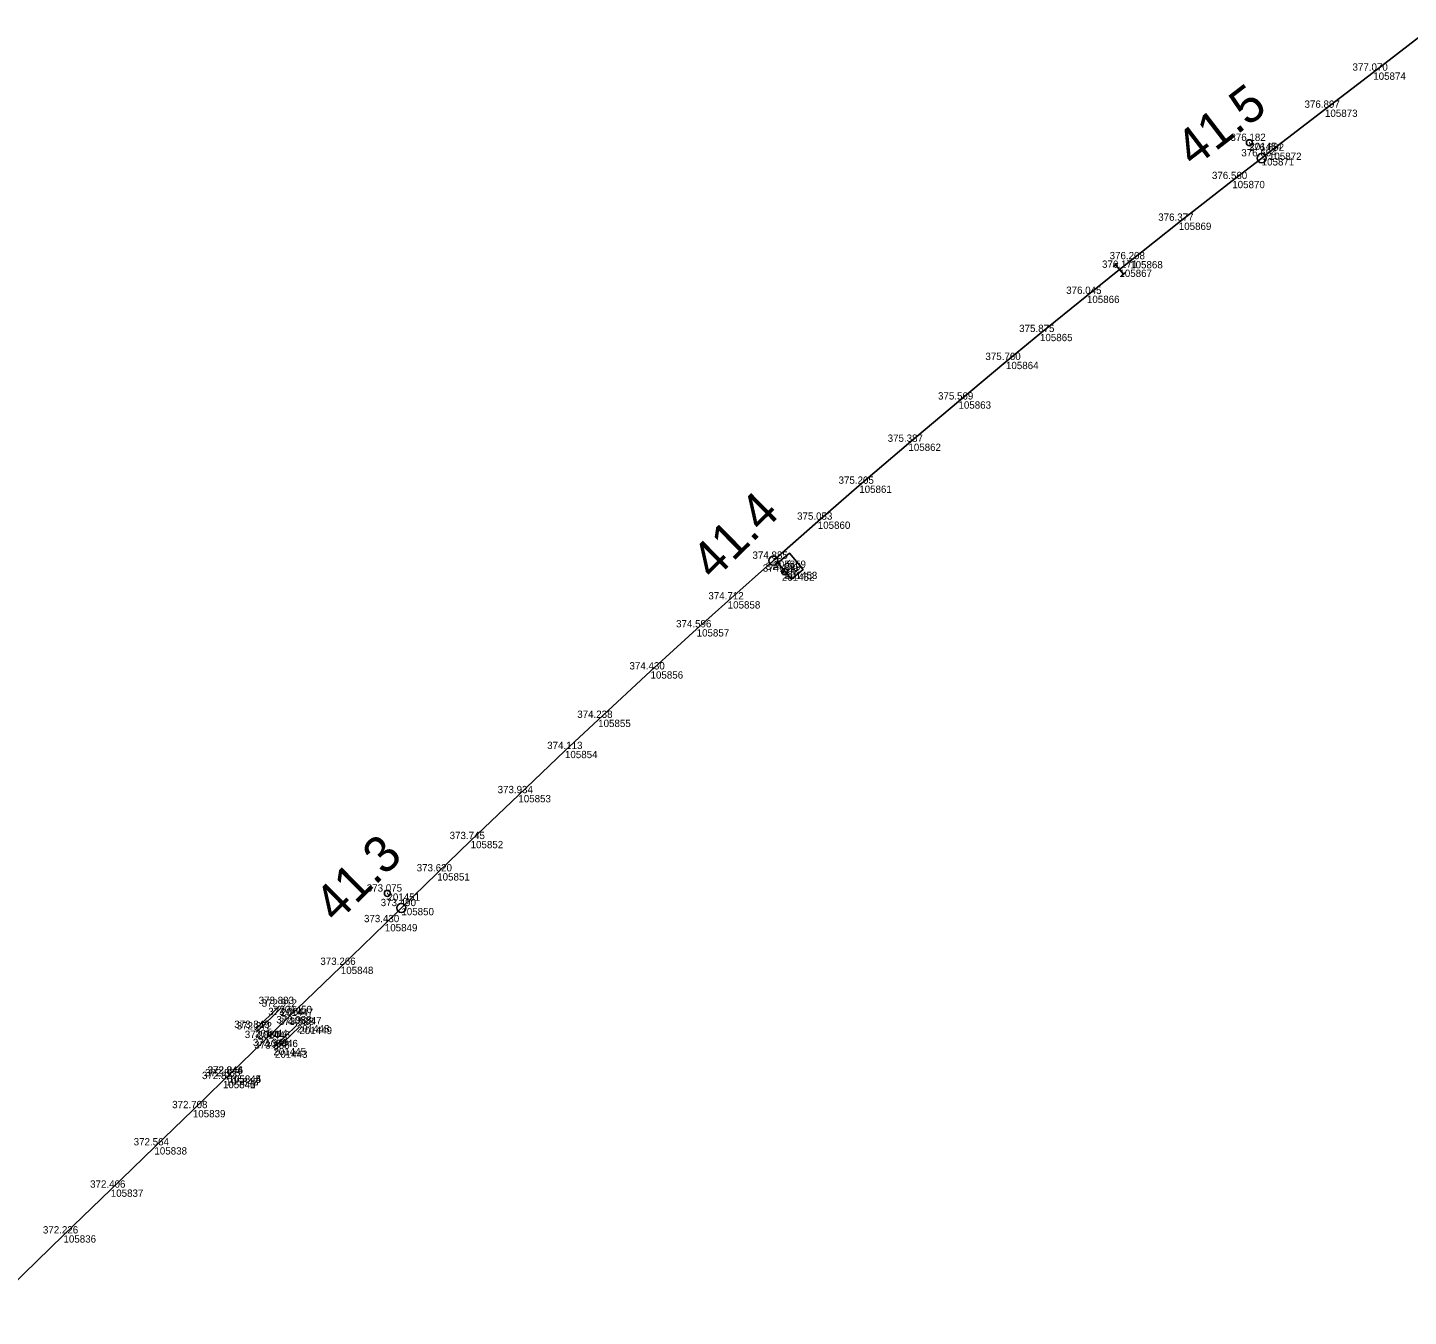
# Model space of a CAD drawing. Extents: x -514522 to -512811, y -1144589 to -1143575.
# Drawn here: x -514321 to -514094, y -1144405.9 to -1144194 of the extents above; entities that cross this region are included whole.
import ezdxf

# ---------------------------------------------------------------- set-up
doc = ezdxf.new("R2010")
doc.units = 0
for name, color, linetype in [('Vrstva 1', 7, 'Continuous'), ('Vrstva 17', 7, 'Continuous'), ('Vrstva 19', 7, 'Continuous'), ('Vrstva 3', 7, 'Continuous'), ('Vrstva 4', 7, 'Continuous'), ('Vrstva 60', 7, 'Continuous'), ('Vrstva 61', 7, 'Continuous'), ('Vrstva 7', 7, 'Continuous')]:
    doc.layers.add(name, color=color, linetype=linetype)

msp = doc.modelspace()

# ---------------------------------------------------------------- linework, layer by layer
at = {"layer": 'Vrstva 1'}
for p, q in [((-514099.77, -1144201.42), (-514090.17, -1144194.04)), ((-514107.71, -1144207.52), (-514099.77, -1144201.42)), ((-514116.92, -1144214.6), (-514107.71, -1144207.52)), ((-514118.11, -1144215.51), (-514116.92, -1144214.6)), ((-514122.95, -1144219.24), (-514118.11, -1144215.51)), ((-514131.74, -1144226.1), (-514122.95, -1144219.24)), ((-514139.73, -1144232.42), (-514131.74, -1144226.1)), ((-514141.5, -1144233.83), (-514139.73, -1144232.42)), ((-514146.84, -1144238.12), (-514141.5, -1144233.83)), ((-514154.56, -1144244.39), (-514146.84, -1144238.12)), ((-514160.15, -1144248.99), (-514154.56, -1144244.39)), ((-514167.96, -1144255.49), (-514160.15, -1144248.99)), ((-514176.19, -1144262.44), (-514167.96, -1144255.49)), ((-514184.27, -1144269.34), (-514176.19, -1144262.44)), ((-514191.09, -1144275.25), (-514184.27, -1144269.34)), ((-514198.39, -1144281.67), (-514191.09, -1144275.25)), ((-514205.89, -1144288.35), (-514198.39, -1144281.67)), ((-514211, -1144292.95), (-514205.89, -1144288.35)), ((-514218.58, -1144299.87), (-514211, -1144292.95)), ((-514227.19, -1144307.83), (-514218.58, -1144299.87)), ((-514232.65, -1144312.95), (-514227.19, -1144307.83)), ((-514240.31, -1144320.21), (-514232.65, -1144312.95)), ((-514248.16, -1144327.76), (-514240.31, -1144320.21)), ((-514253.65, -1144333.07), (-514248.16, -1144327.76)), ((-514259.54, -1144338.78), (-514253.65, -1144333.07)), ((-514262.26, -1144341.42), (-514259.54, -1144338.78)), ((-514269.5, -1144348.44), (-514262.26, -1144341.42)), ((-514278.02, -1144356.7), (-514269.5, -1144348.44)), ((-514281.91, -1144360.46), (-514278.02, -1144356.7)), ((-514287.96, -1144366.32), (-514281.91, -1144360.46)), ((-514288.88, -1144367.22), (-514288.4, -1144366.75)), ((-514288.4, -1144366.75), (-514287.96, -1144366.32)), ((-514293.82, -1144372), (-514288.88, -1144367.22)), ((-514300.14, -1144378.12), (-514293.82, -1144372)), ((-514307.31, -1144385.07), (-514300.14, -1144378.12)), ((-514315.09, -1144392.6), (-514307.31, -1144385.07)), ((-514328.85, -1144405.93), (-514315.09, -1144392.6))]:
    msp.add_line(p, q, dxfattribs=at)
at = {"layer": 'Vrstva 17'}
for p, q in [((-514283.6, -1144358.8), (-514279.59, -1144354.87)), ((-514280.33, -1144362.22), (-514276.3, -1144358.32))]:
    msp.add_line(p, q, dxfattribs=at)
at = {"layer": 'Vrstva 19'}
for p, q in [((-514283.21, -1144359.05), (-514279.39, -1144355.32)), ((-514280.57, -1144361.79), (-514276.72, -1144358.04))]:
    msp.add_line(p, q, dxfattribs=at)
at = {"layer": 'Vrstva 3'}
for p, q in [((-514142.52, -1144233.38), (-514141.76, -1144232.74)), ((-514142.14, -1144233.06), (-514140.85, -1144234.59)), ((-514141.24, -1144234.91), (-514140.47, -1144234.27))]:
    msp.add_line(p, q, dxfattribs=at)
at = {"layer": 'Vrstva 4'}
msp.add_line((-514160.15, -1144248.99), (-514154.56, -1144244.39), dxfattribs=at)
at = {"layer": 'Vrstva 60'}
for p, q in [((-514099.77, -1144201.42), (-514099.77, -1144201.42)), ((-514107.71, -1144207.52), (-514107.71, -1144207.52)), ((-514120.13, -1144212.97), (-514120.13, -1144212.97)), ((-514116.92, -1144214.6), (-514116.92, -1144214.6)), ((-514118.11, -1144215.51), (-514118.11, -1144215.51)), ((-514122.95, -1144219.24), (-514122.95, -1144219.24)), ((-514131.74, -1144226.1), (-514131.74, -1144226.1)), ((-514139.73, -1144232.42), (-514139.73, -1144232.42)), ((-514141.5, -1144233.83), (-514141.5, -1144233.83)), ((-514146.84, -1144238.12), (-514146.84, -1144238.12)), ((-514154.56, -1144244.39), (-514154.56, -1144244.39)), ((-514160.15, -1144248.99), (-514160.15, -1144248.99)), ((-514167.96, -1144255.49), (-514167.96, -1144255.49)), ((-514176.19, -1144262.44), (-514176.19, -1144262.44)), ((-514184.27, -1144269.34), (-514184.27, -1144269.34)), ((-514191.09, -1144275.25), (-514191.09, -1144275.25)), ((-514198.39, -1144281.67), (-514198.39, -1144281.67)), ((-514196.99, -1144283.79), (-514196.99, -1144283.79)), ((-514196.52, -1144283.5), (-514196.52, -1144283.5)), ((-514205.89, -1144288.35), (-514205.89, -1144288.35)), ((-514211, -1144292.95), (-514211, -1144292.95)), ((-514218.58, -1144299.87), (-514218.58, -1144299.87)), ((-514227.19, -1144307.83), (-514227.19, -1144307.83)), ((-514232.65, -1144312.95), (-514232.65, -1144312.95)), ((-514240.31, -1144320.21), (-514240.31, -1144320.21)), ((-514248.16, -1144327.76), (-514248.16, -1144327.76)), ((-514253.65, -1144333.07), (-514253.65, -1144333.07)), ((-514261.83, -1144336.39), (-514261.83, -1144336.39)), ((-514259.54, -1144338.78), (-514259.54, -1144338.78)), ((-514262.26, -1144341.42), (-514262.26, -1144341.42)), ((-514269.5, -1144348.44), (-514269.5, -1144348.44)), ((-514279.59, -1144354.87), (-514279.59, -1144354.87)), ((-514279.39, -1144355.32), (-514279.39, -1144355.32)), ((-514278.02, -1144356.7), (-514278.02, -1144356.7)), ((-514283.6, -1144358.8), (-514283.6, -1144358.8)), ((-514283.21, -1144359.05), (-514283.21, -1144359.05)), ((-514276.72, -1144358.04), (-514276.72, -1144358.04)), ((-514276.3, -1144358.32), (-514276.3, -1144358.32)), ((-514281.91, -1144360.46), (-514281.91, -1144360.46)), ((-514280.57, -1144361.79), (-514280.57, -1144361.79)), ((-514280.33, -1144362.22), (-514280.33, -1144362.22)), ((-514288.4, -1144366.75), (-514288.4, -1144366.75)), ((-514288.4, -1144366.75), (-514288.4, -1144366.75)), ((-514287.96, -1144366.32), (-514287.96, -1144366.32)), ((-514287.95, -1144366.32), (-514287.95, -1144366.32)), ((-514288.88, -1144367.21), (-514288.88, -1144367.21)), ((-514288.88, -1144367.22), (-514288.88, -1144367.22)), ((-514293.82, -1144372), (-514293.82, -1144372)), ((-514300.14, -1144378.12), (-514300.14, -1144378.12)), ((-514307.31, -1144385.07), (-514307.31, -1144385.07)), ((-514315.09, -1144392.6), (-514315.09, -1144392.6))]:
    msp.add_line(p, q, dxfattribs=at)
at = {"layer": 'Vrstva 7'}
for p, q in [((-514120.18, -1144212.97), (-514120.08, -1144212.97)), ((-514196.99, -1144283.79), (-514196.51, -1144283.39)), ((-514196.57, -1144283.5), (-514196.47, -1144283.5)), ((-514261.88, -1144336.39), (-514261.78, -1144336.39))]:
    msp.add_line(p, q, dxfattribs=at)
msp.add_lwpolyline([(-514197.63, -1144282.05), (-514195.73, -1144280.46), (-514193.49, -1144283.13), (-514195.39, -1144284.73)], close=True, dxfattribs=at)
for centre, radius in [((-514120.13, -1144212.97), 0.5), ((-514118.11, -1144215.51), 0.75), ((-514198.39, -1144281.67), 0.75), ((-514196.52, -1144283.5), 0.5), ((-514261.83, -1144336.39), 0.5), ((-514259.54, -1144338.78), 0.75)]:
    msp.add_circle(centre, radius, dxfattribs=at)

# ---------------------------------------------------------------- texts
at = {"layer": 'Vrstva 60'}
for s, p in [('105874', (-514099.77, -1144202.62)), ('105873', (-514107.71, -1144208.72)), ('201454', (-514120.13, -1144214.17)), ('105872', (-514116.92, -1144215.8)), ('105871', (-514118.11, -1144216.71)), ('105870', (-514122.95, -1144220.44)), ('105869', (-514131.74, -1144227.3)), ('105868', (-514139.73, -1144233.62)), ('105867', (-514141.5, -1144235.03)), ('105866', (-514146.84, -1144239.32)), ('105865', (-514154.56, -1144245.59)), ('105864', (-514160.15, -1144250.19)), ('105863', (-514167.96, -1144256.69)), ('105862', (-514176.19, -1144263.64)), ('105861', (-514184.27, -1144270.54)), ('105860', (-514191.09, -1144276.45)), ('105859', (-514198.39, -1144282.87)), ('201452', (-514196.99, -1144284.99)), ('201453', (-514196.52, -1144284.7)), ('105858', (-514205.89, -1144289.55)), ('105857', (-514211, -1144294.15)), ('105856', (-514218.58, -1144301.07)), ('105855', (-514227.19, -1144309.03)), ('105854', (-514232.65, -1144314.15)), ('105853', (-514240.31, -1144321.41)), ('105852', (-514248.16, -1144328.96)), ('105851', (-514253.65, -1144334.27)), ('201451', (-514261.83, -1144337.59)), ('105850', (-514259.54, -1144339.98)), ('105849', (-514262.26, -1144342.62)), ('105848', (-514269.5, -1144349.64)), ('201450', (-514279.59, -1144356.07)), ('201447', (-514279.39, -1144356.52)), ('105847', (-514278.02, -1144357.9)), ('201444', (-514283.6, -1144360)), ('201446', (-514283.21, -1144360.25)), ('201448', (-514276.72, -1144359.24)), ('201449', (-514276.3, -1144359.52)), ('105846', (-514281.91, -1144361.66)), ('201445', (-514280.57, -1144362.99)), ('201443', (-514280.33, -1144363.42)), ('105842', (-514288.4, -1144367.95)), ('105843', (-514288.4, -1144367.95)), ('105844', (-514287.96, -1144367.52)), ('105845', (-514287.95, -1144367.52)), ('105840', (-514288.88, -1144368.42)), ('105841', (-514288.88, -1144368.41)), ('105839', (-514293.82, -1144373.2)), ('105838', (-514300.14, -1144379.32)), ('105837', (-514307.31, -1144386.27)), ('105836', (-514315.09, -1144393.8))]:
    msp.add_text(s, height=1.2, dxfattribs=at).set_placement(p)
at = {"layer": 'Vrstva 61'}
for s, p in [('377.070', (-514103.18, -1144201.12)), ('376.897', (-514111.07, -1144207.22)), ('376.182', (-514123.25, -1144212.67)), ('376.664', (-514121.46, -1144215.21)), ('376.692', (-514120.24, -1144214.3)), ('376.560', (-514126.29, -1144218.94)), ('376.377', (-514135.12, -1144225.8)), ('376.171', (-514144.36, -1144233.53)), ('376.208', (-514143.11, -1144232.12)), ('376.045', (-514150.25, -1144237.82)), ('375.875', (-514157.98, -1144244.09)), ('375.760', (-514163.53, -1144248.69)), ('375.569', (-514171.32, -1144255.19)), ('375.387', (-514179.6, -1144262.14)), ('375.205', (-514187.67, -1144269.04)), ('375.053', (-514194.49, -1144274.95)), ('374.885', (-514201.82, -1144281.37)), ('374.109', (-514200.13, -1144283.49)), ('374.619', (-514199.64, -1144283.2)), ('374.712', (-514209.07, -1144288.05)), ('374.596', (-514214.38, -1144292.65)), ('374.430', (-514222.04, -1144299.57)), ('374.238', (-514230.63, -1144307.53)), ('374.113', (-514235.57, -1144312.65)), ('373.934', (-514243.72, -1144319.91)), ('373.745', (-514251.61, -1144327.46)), ('373.620', (-514257.02, -1144332.77)), ('373.075', (-514265.23, -1144336.09)), ('373.490', (-514262.94, -1144338.48)), ('373.430', (-514265.69, -1144341.12)), ('373.266', (-514272.86, -1144348.14)), ('373.883', (-514283, -1144354.57)), ('372.912', (-514282.51, -1144355.02)), ('373.064', (-514281.43, -1144356.4)), ('373.849', (-514287.01, -1144358.5)), ('372.872', (-514286.62, -1144358.75)), ('372.933', (-514280.1, -1144357.74)), ('373.928', (-514279.68, -1144358.02)), ('372.980', (-514285.28, -1144360.16)), ('372.949', (-514283.95, -1144361.49)), ('373.955', (-514283.71, -1144361.92)), ('372.824', (-514292.32, -1144366.92)), ('372.824', (-514292.32, -1144366.91)), ('372.833', (-514291.81, -1144366.45)), ('372.835', (-514291.81, -1144366.45)), ('372.844', (-514291.42, -1144366.02)), ('372.846', (-514291.36, -1144366.02)), ('372.708', (-514297.22, -1144371.7)), ('372.564', (-514303.55, -1144377.82)), ('372.406', (-514310.71, -1144384.77)), ('372.226', (-514318.47, -1144392.3))]:
    msp.add_text(s, height=1.2, dxfattribs=at).set_placement(p)
at = {"layer": 'Vrstva 7'}
for s, height, rotation, p in [('41.5', 6, 37.535, (-514129.29, -1144217.19)), ('41.4', 6, 44.5893, (-514208.24, -1144285.09)), ('KM', 1.247, 310, (-514196.69, -1144282.21)), ('41.3', 6, 44.5893, (-514270.23, -1144341.44))]:
    msp.add_text(s, height=height, rotation=rotation, dxfattribs=at).set_placement(p)

doc.saveas('drawing.dxf')
